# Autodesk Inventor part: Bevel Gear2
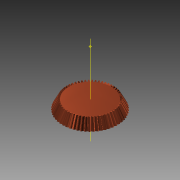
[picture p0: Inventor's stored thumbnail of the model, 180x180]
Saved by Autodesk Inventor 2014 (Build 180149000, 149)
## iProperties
Created: 2008-07
Part Number: Bevel Gear2
Material: Steel, Mild
Document SubType Name: Modeling
Designer: tangg
Categories: <?xml version="1.0" encoding="UTF-16"?> <MemberInstance><Categories><FamilyTemplate><FamilyTemplateParameter ValueType="xs:double" Id="1" ObjectReferenceKey="da
Mass: 60.9118 g
Surface Area: 34.3074 cm^2
Volume: 7.7496 cm^3
Density: 7.86 g/cm^3
Appearance: Copper - Polished
CustomPartVersion: 1
Author: tangg
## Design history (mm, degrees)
node "Top Point"
node "Mesh Plane2"
sketch "Teeth Body Sketch"
  geometry: L1 (0, 0)-(19.196, -41.108); L2 (19.196, -41.108)-(20.579, -40.431); L3 (20.579, -40.431)-(0, 0); L4 (19.95, -40.739)-(0, 0); L5 (15.81, -33.858)-(16.949, -33.301); L6 (19.196, -41.108)-(15.81, -33.858); L7 (20.579, -40.431)-(16.949, -33.301); L8 (0, -49.33)-(0, 8.222) reference; L9 (0, -40.739)-(20.579, -40.739)
  constraints: 16 end point, 4 point on line, 3 perpendicular, 2 collinear, 1 horizontal alignment, 1 vertical alignment
  dimensions: "d0" = 39.9 diameter of L4.start L8 (= da_de); "d1" = 38.3912 diameter of L1.end L8 (= da_dfe); "d2" = 41.15733 diameter of L2.end L8 (= da_dae); "d3" = 8 distance between parallel lines of L2 L5 (= da_b); "d4" = 40.43108 vertical distance of L2.end L1.start (= da_ve)
revolve "Teeth Body" sketch "Teeth Body Sketch" stored, may be unused: angle "d5" = 90 deg
node "Start Point"
node "Tooth Plane"
sketch "Start Sketch"
  geometry: L1 (0, -48.837)-(0, 14.035) reference; L2 (-0.213, -0.185)-(0.213, -0.185); A1 r 8.268 centre (-8.214, -2.267) between (-0.213, -0.185) and (-1.118, 1.975); A2 r 8.268 centre (8.214, -2.267) between (1.118, 1.975) and (0.213, -0.185); A3 r 23.376 centre (0, -21.374) between (1.118, 1.975) and (-1.118, 1.975); 1 further point
  constraints: 6 point on circle, 3 centre point, 3 symmetric about line, 2 end point, 1 coincident, 1 perpendicular, 1 other
  dimensions: "d7" = 8.26757 radius of A1 (= fd_rr); "d8" = 8.21392 horizontal distance of point (0, -21.374) A1.centre (= fd_x); "d9" = 19.10643 vertical distance of point (0, -21.374) A1.centre (= fd_y); "d57" = 23.37567 radius of A3 (= 0.5 x fd_dva + 0.3 x da_he); "d58" = 21.18887 distance from line of A3.centre L2 (= 0.5 x fd_dva - 1.12 x da_he)
node "End Point"
  node "End Plane"
sketch "3D Sketch Right"
  node "Helical Curve Right" dims "d65" = 1118.46783 (computed from da_dm, da_delta, da_beta), "d66" = 31.5, "d67" = 39.9 (= da_de), "d68" = -4.55377 (= -da_delta), "d69" = 7.25392 (computed from fd_loft, da_delta)
node "End Plane Right"
sketch "End Sketch Right"
  geometry: L1 (0, -22.799)-(0, 5.523) reference; L2 (-0.175, -0.821)-(0.175, -0.821); A1 r 6.804 centre (-6.76, -2.535) between (-0.175, -0.821) and (-0.92, 0.956); A2 r 6.804 centre (6.76, -2.535) between (0.92, 0.956) and (0.175, -0.821); A3 r 19.237 centre (0, -18.258) between (0.92, 0.956) and (-0.92, 0.956); 1 further point
  constraints: 6 point on circle, 3 centre point, 3 symmetric about line, 2 end point, 1 coincident, 1 perpendicular, 1 other
  dimensions: "d70" = 6.75958 horizontal distance of A3.centre A1.centre (computed from fd_x, fd_ratio); "d71" = 15.72347 vertical distance of point (0, -18.258) A1.centre (computed from fd_y, fd_ratio); "d72" = 6.80373 radius of A1 (computed from fd_rr, fd_ratio); "d73" = 17.4372 distance from line of point (0, -18.258) L2 (computed from d58, fd_ratio); "d74" = 19.23681 radius of A3 (computed from d57, fd_ratio)
feature "Loft Right" sketch "End Sketch Right" dims "d75" = 0, "d76" = 90 deg, "d77" = 0, "d78" = 90 deg, "d79" = 0, "d80" = 90 deg, "d85" = 20, "da_teethtype" = 0 [user parameter]
sketch "3D Sketch Left"
  node "Helical Curve Left" dims "d26" = 1118.46783 (computed from da_dm, da_delta, da_beta), "d27" = 7.25392 (computed from fd_loft, da_delta), "d28" = 39.9 (= da_de), "d29" = -4.55377 (= -da_delta)
node "End Plane Left"
sketch "End Sketch Left" dims "d56" = 15.22216 (derived)
  geometry: L1 (0, -37.75)-(0, 8.865) reference; L2 (-0.175, -0.821)-(0.175, -0.821); A1 r 6.804 centre (-6.76, -2.535) between (-0.175, -0.821) and (-0.92, 0.956); A2 r 6.804 centre (6.76, -2.535) between (0.92, 0.956) and (0.175, -0.821); A3 r 19.237 centre (0, -18.258) between (0.92, 0.956) and (-0.92, 0.956); 2 further points; 1 other entity
  constraints: 6 point on circle, 3 centre point, 3 symmetric about line, 2 end point, 1 coincident, 2 other
  dimensions: "d30" = 6.80373 radius of A1 (computed from fd_rr, fd_ratio); "d31" = 6.75958 horizontal distance of point (0, -18.258) A1.centre (computed from fd_x, fd_ratio); "d32" = 15.72347 vertical distance of A1.centre point (0, -18.258) (computed from fd_y, fd_ratio); "d61" = 19.23681 radius of A3 (computed from d57, fd_ratio); "d62" = 17.4372 distance from line of point (0, -18.258) L2 (computed from d58, fd_ratio)
feature "Loft Left" sketch "End Sketch Left" dims "d35" = 0, "d37" = 0, "d39" = 0, "d40" = 90 deg, "d63" = 90 deg, "d64" = 90 deg, "d84" = 10, "da_teethtype" = 0 [user parameter]
sketch "Body Sketch"
  geometry: L1 (0, -42.558)-(0, -32.408) reference; L2 (19.196, -41.108)-(15.81, -33.858) reference; L3 (15.81, -33.858)-(0, -33.858); L4 (19.196, -41.108)-(0, -41.108)
  constraints: 4 end point, 2 perpendicular, 2 point on line
revolve "Fix Body" sketch "Body Sketch" stored, may be unused: angle "d46" = 90 deg
sketch "Sketch6"
  geometry: L1 (19.95, -40.739)-(0, 0) reference; L2 (0, -48.887)-(0, 8.148) reference
feature "Pitch Diameter" sketch "Sketch6" dims angle "d47" = 90 deg
body "Solid1"
feature "Loft" dims "d17" = 0, "d18" = 90 deg, "d19" = 0, "d20" = 90 deg, "d89" = 0, "da_teethtype" = 0 [user parameter]
pattern_circular "Circular Pattern" dims angle "d22" = 360 deg, "d88" = 0, "da_teethtype" = 0 [user parameter]
pattern_circular "Circular Pattern Right" dims angle "d82" = 360 deg, "da_teethtype" = 0 [user parameter]
pattern_circular "Circular Pattern Left" dims angle "d42" = 360 deg, "da_teethtype" = 0 [user parameter]
sketch "End Sketch"
  geometry: L1 (0, -44.037)-(0, 12.922) reference; L2 (-0.175, 0.019)-(0.175, 0.019); A1 r 6.804 centre (-6.76, -1.695) between (-0.175, 0.019) and (-0.92, 1.796); A2 r 6.804 centre (6.76, -1.695) between (0.92, 1.796) and (0.175, 0.019); A3 r 19.237 centre (0, -17.418) between (0.92, 1.796) and (-0.92, 1.796); 1 further point
  constraints: 6 point on circle, 3 centre point, 3 symmetric about line, 2 end point, 1 coincident, 1 other
  dimensions: "d12" = 6.80373 radius of A1 (computed from fd_rr, fd_ratio); "d15" = 6.75958 horizontal distance of A1.centre point (0, -17.418) (computed from fd_x, fd_ratio); "d16" = 15.72347 vertical distance of A1.centre point (0, -17.418) (computed from fd_y, fd_ratio); "d59" = 19.23681 radius of A3 (computed from d57, fd_ratio); "d60" = 17.4372 distance from line of A3.centre L2 (computed from d58, fd_ratio)
body "Srf1"
other parameters: "da_b" = 8 [user parameter; used in 2 equation terms], "da_de" = 39.9 [user parameter; used in 4 equation terms], "da_dae" = 41.15733 [user parameter; used in 2 equation terms], "da_dfe" = 38.3912 [user parameter; used in 1 equation term], "da_le" = 45.36148 [user parameter; used in 1 equation term], "da_omega" = 45 deg [user parameter], "da_beta" = 0 [user parameter; used in 2 equation terms], "da_delta" = 4.55377 [user parameter; used in 8 equation terms], "da_alpha" = 20 deg [user parameter; used in 1 equation term], "da_he" = 1.54 [user parameter; used in 4 equation terms], "da_ve" = 40.43108 [user parameter; used in 1 equation term], "fd_dv" = 44.42735 (computed from da_de, da_delta) [user parameter; used in 1 equation term], "fd_dva" = 45.82735 (computed from da_dae, da_delta) [user parameter; used in 3 equation terms], "fd_dvb" = 41.74805 (computed from fd_dv, da_alpha) [user parameter; used in 2 equation terms], "da_zv" = 634.67638 [user parameter; used in 1 equation term], "fd_loft" = 8.077 (= da_b + 0.05 x da_he) [user parameter; used in 4 equation terms], "fd_ratio" = 8.22941 (computed from da_le, fd_loft) [user parameter; used in 15 equation terms], "fd_rr" = 8.26757 (computed from fd_dd, fd_dvb) [user parameter; used in 6 equation terms], "fd_angle" = 0.2475 (computed from da_zv) [user parameter; used in 4 equation terms], "fd_x1" = 0.54972 (computed from da_dvw, fd_angle) [user parameter; used in 1 equation term], "fd_y1" = 22.20687 (computed from da_dvw, fd_angle) [user parameter; used in 1 equation term], "fd_x2" = 7.6642 (computed from fd_rr, fd_angle2, fd_angle) [user parameter; used in 1 equation term], "fd_y2" = 3.10044 (computed from fd_rr, fd_angle2, fd_angle) [user parameter; used in 1 equation term], "fd_x" = 8.21392 (= fd_x1 + fd_x2) [user parameter; used in 4 equation terms], "fd_y" = 19.10643 (= fd_y1 - fd_y2) [user parameter; used in 4 equation terms], "fd_angle2" = 3.5966 (computed from fd_dvb, fd_dd) [user parameter; used in 2 equation terms], "fd_dd" = 44.90335 (= fd_dva - 0.6 x da_he) [user parameter; used in 2 equation terms], "da_dvw" = 44.42735 [user parameter; used in 2 equation terms], "d11" = -8.077 (= -fd_loft), "da_dm" = 36.3816 [user parameter; used in 2 equation terms], "da_x" = 0 [user parameter], "da_m" = 0.7 [user parameter], "d51" = 0.55116 (computed from da_z)
